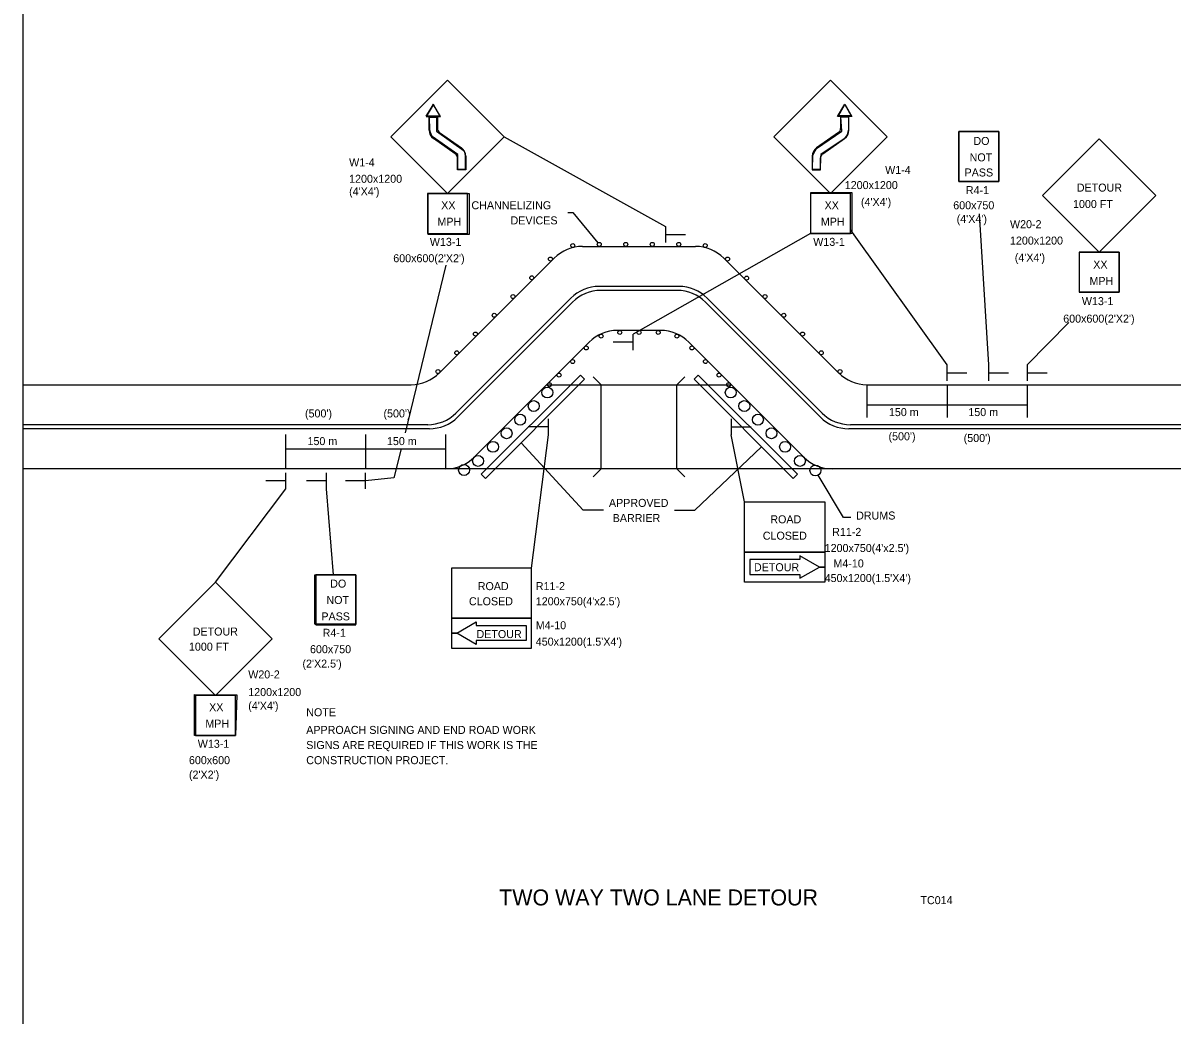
# Model space of a CAD drawing. Extents: x 1100953.92 to 1100956.78, y 416755.57 to 416757.4.
# Drawn here: x 1100955.836 to 1100956.434, y 416756.372 to 416756.888 of the extents above; entities that cross this region are included whole.
import ezdxf

# ---------------------------------------------------------------- set-up
doc = ezdxf.new("R2010")
doc.units = 0
for name, color, linetype in [('GROUND TEXT', 7, 'Continuous'), ('H_V CNTRL TEXT', 7, 'Continuous'), ('H_V CONTROLS', 7, 'Continuous'), ('Level 11', 7, 'Continuous'), ('Level 33', 7, 'Continuous'), ('Level 5', 7, 'Continuous'), ('ORIG TOPO TEXT', 7, 'Continuous')]:
    doc.layers.add(name, color=color, linetype=linetype)

msp = doc.modelspace()

# ---------------------------------------------------------------- linework, layer by layer
at = {"layer": 'GROUND TEXT'}
for centre in [(1100956.10844, 416756.69561), (1100956.20386, 416756.69561), (1100956.10137, 416756.68855), (1100956.21093, 416756.68855), (1100956.09431, 416756.68148), (1100956.21799, 416756.68148), (1100956.08724, 416756.67442), (1100956.22506, 416756.67442), (1100956.08018, 416756.66735), (1100956.23212, 416756.66735), (1100956.07243, 416756.66003), (1100956.23987, 416756.66003), (1100956.06513, 416756.6553), (1100956.2479, 416756.65504)]:
    msp.add_circle(centre, 0.00284, dxfattribs=at)
at = {"layer": 'H_V CNTRL TEXT'}
for p, q in [((1100956.1268, 416756.77166), (1100956.1855, 416756.77166)), ((1100956.0523, 416756.70579), (1100956.11207, 416756.76556)), ((1100956.20023, 416756.76556), (1100956.26, 416756.70579)), ((1100956.17687, 416756.75083), (1100956.13543, 416756.75083)), ((1100956.17601, 416756.74875), (1100956.13629, 416756.74875)), ((1100956.1207, 416756.74473), (1100956.06093, 416756.68496)), ((1100956.12156, 416756.74264), (1100956.06179, 416756.68287)), ((1100956.25051, 416756.68287), (1100956.19074, 416756.74264)), ((1100956.25137, 416756.68496), (1100956.1916, 416756.74473)), ((1100956.16738, 416756.72791), (1100956.14492, 416756.72791)), ((1100956.13019, 416756.72181), (1100956.07042, 416756.66204)), ((1100956.24188, 416756.66204), (1100956.18211, 416756.72181)), ((1100955.83571, 416756.69969), (1100956.03757, 416756.69969)), ((1100956.10807, 416756.69969), (1100956.20423, 416756.69969)), ((1100956.27473, 416756.69969), (1100956.45743, 416756.69969)), ((1100956.27473, 416756.69969), (1100956.27473, 416756.68266)), ((1100956.3164, 416756.69969), (1100956.3164, 416756.68266)), ((1100956.35807, 416756.69969), (1100956.35807, 416756.68266)), ((1100956.04619, 416756.67885), (1100955.83571, 416756.67885)), ((1100956.04706, 416756.67677), (1100955.83571, 416756.67677)), ((1100956.45743, 416756.67677), (1100956.26524, 416756.67677)), ((1100956.45743, 416756.67885), (1100956.2661, 416756.67885)), ((1100955.97235, 416756.65594), (1100955.97235, 416756.67383)), ((1100956.01402, 416756.65594), (1100956.01402, 416756.67383)), ((1100956.05569, 416756.65594), (1100956.05569, 416756.67383)), ((1100956.05569, 416756.65594), (1100955.83571, 416756.65594)), ((1100956.25661, 416756.65594), (1100956.05569, 416756.65594)), ((1100956.45743, 416756.65594), (1100956.25661, 416756.65594))]:
    msp.add_line(p, q, dxfattribs=at)
for points in [[(1100956.11908, 416756.78927), (1100956.12174, 416756.78927), (1100956.13479, 416756.77351)], [(1100956.12783, 416756.70249), (1100956.12562, 416756.7047), (1100956.07406, 416756.65314), (1100956.07627, 416756.65093), (1100956.12783, 416756.70249)], [(1100956.18697, 416756.7047), (1100956.18476, 416756.70249), (1100956.23632, 416756.65093), (1100956.23853, 416756.65314), (1100956.18697, 416756.7047)], [(1100956.13232, 416756.65177), (1100956.13648, 416756.65594), (1100956.13648, 416756.69969), (1100956.13232, 416756.70385)], [(1100956.17998, 416756.65177), (1100956.17582, 416756.65594), (1100956.17582, 416756.69969), (1100956.17998, 416756.70385)], [(1100956.13775, 416756.63434), (1100956.12705, 416756.63434), (1100956.09477, 416756.66943)], [(1100956.17455, 416756.63434), (1100956.18525, 416756.63434), (1100956.21987, 416756.66738)], [(1100956.26637, 416756.6306), (1100956.26257, 416756.6306), (1100956.24936, 416756.6526)]]:
    msp.add_lwpolyline(points, dxfattribs=at)
for centre, start, end in [((1100956.1268, 416756.75083), 90, 135), ((1100956.1855, 416756.75083), 45, 90), ((1100956.13543, 416756.73), 90, 135), ((1100956.13629, 416756.72791), 90, 135), ((1100956.17601, 416756.72791), 45, 90), ((1100956.17687, 416756.73), 45, 90), ((1100956.14492, 416756.70708), 90, 135), ((1100956.16738, 416756.70708), 45, 90), ((1100956.03757, 416756.72052), 270, 315), ((1100956.27473, 416756.72052), 225, 270), ((1100956.04619, 416756.69969), 270, 315), ((1100956.04706, 416756.6976), 270, 315), ((1100956.26524, 416756.6976), 225, 270), ((1100956.2661, 416756.69969), 225, 270), ((1100956.05569, 416756.67677), 270, 315), ((1100956.25661, 416756.67677), 225, 270)]:
    msp.add_arc(centre, 0.02083, start, end, dxfattribs=at)
at = {"layer": 'Level 11'}
for p, q in [((1100956.26101, 416756.83923), (1100956.26101, 416756.83304)), ((1100956.05239, 416756.8309), (1100956.0638, 416756.8229)), ((1100956.25991, 416756.8309), (1100956.2485, 416756.8229)), ((1100956.06057, 416756.81987), (1100956.04916, 416756.82787)), ((1100956.08594, 416756.82863), (1100956.16985, 416756.78198)), ((1100956.25173, 416756.81987), (1100956.26314, 416756.82787)), ((1100956.34325, 416756.80533), (1100956.34337, 416756.80544)), ((1100956.33316, 416756.78867), (1100956.33791, 416756.71004)), ((1100956.2454, 416756.77834), (1100956.15316, 416756.72605)), ((1100956.16985, 416756.78198), (1100956.16985, 416756.77365)), ((1100956.16985, 416756.77781), (1100956.18027, 416756.77781)), ((1100956.26623, 416756.78012), (1100956.31629, 416756.71004)), ((1100956.38507, 416756.76865), (1100956.38507, 416756.74781)), ((1100956.05571, 416756.76186), (1100956.0344, 416756.67469)), ((1100956.3797, 416756.73198), (1100956.35806, 416756.71004)), ((1100956.15316, 416756.71772), (1100956.15316, 416756.72605)), ((1100956.15316, 416756.72189), (1100956.14274, 416756.72189)), ((1100956.31629, 416756.71004), (1100956.31629, 416756.7017)), ((1100956.31629, 416756.70587), (1100956.3267, 416756.70587)), ((1100956.33791, 416756.71004), (1100956.33791, 416756.7017)), ((1100956.33791, 416756.70587), (1100956.34833, 416756.70587)), ((1100956.35806, 416756.71004), (1100956.35806, 416756.7017)), ((1100956.35806, 416756.70587), (1100956.36848, 416756.70587)), ((1100956.27473, 416756.68927), (1100956.3164, 416756.68927)), ((1100956.3164, 416756.68927), (1100956.35807, 416756.68927)), ((1100956.10898, 416756.67365), (1100956.10898, 416756.68198)), ((1100956.20416, 416756.68198), (1100956.20416, 416756.67365)), ((1100956.10898, 416756.67781), (1100956.09856, 416756.67781)), ((1100956.20416, 416756.67781), (1100956.21457, 416756.67781)), ((1100956.10022, 416756.60429), (1100956.10898, 416756.67365)), ((1100956.21109, 416756.63868), (1100956.20416, 416756.67365)), ((1100955.97235, 416756.66635), (1100956.01402, 416756.66635)), ((1100956.01402, 416756.66635), (1100956.05569, 416756.66635)), ((1100955.97242, 416756.64548), (1100955.97242, 416756.65381)), ((1100955.99359, 416756.64548), (1100955.99359, 416756.65381)), ((1100956.01392, 416756.64548), (1100956.01392, 416756.65381)), ((1100955.93581, 416756.59698), (1100955.97242, 416756.64548)), ((1100955.97242, 416756.64964), (1100955.962, 416756.64964)), ((1100955.99359, 416756.64964), (1100955.98317, 416756.64964)), ((1100955.99728, 416756.60077), (1100955.99359, 416756.64548)), ((1100956.01392, 416756.64964), (1100956.0035, 416756.64964)), ((1100955.98805, 416756.57473), (1100955.98793, 416756.57485))]:
    msp.add_line(p, q, dxfattribs=at)
for points in [[(1100956.02702, 416756.82863), (1100956.05648, 416756.79917), (1100956.08594, 416756.82863), (1100956.05648, 416756.8581), (1100956.02702, 416756.82863)], [(1100956.28528, 416756.82863), (1100956.25582, 416756.79917), (1100956.22636, 416756.82863), (1100956.25582, 416756.8581), (1100956.28528, 416756.82863)], [(1100956.04536, 416756.83923), (1100956.05286, 416756.83923), (1100956.04911, 416756.84573), (1100956.04536, 416756.83923)], [(1100956.26693, 416756.83923), (1100956.25943, 416756.83923), (1100956.26318, 416756.84573), (1100956.26693, 416756.83923)], [(1100956.04694, 416756.83213), (1100956.04694, 416756.83923), (1100956.05129, 416756.83923), (1100956.05129, 416756.83304)], [(1100956.26535, 416756.83213), (1100956.26535, 416756.83923), (1100956.26101, 416756.83923)], [(1100956.34337, 416756.83137), (1100956.34337, 416756.80533), (1100956.32254, 416756.80533), (1100956.32254, 416756.83137), (1100956.34337, 416756.83137)], [(1100956.32254, 416756.83137), (1100956.32254, 416756.80533), (1100956.34337, 416756.80533), (1100956.34337, 416756.83137), (1100956.32254, 416756.83137)], [(1100956.42495, 416756.79811), (1100956.39549, 416756.76865), (1100956.36603, 416756.79811), (1100956.39549, 416756.82757), (1100956.42495, 416756.79811)], [(1100956.06602, 416756.81864), (1100956.06602, 416756.81154), (1100956.06168, 416756.81154), (1100956.06168, 416756.81773)], [(1100956.24628, 416756.81864), (1100956.24628, 416756.81154), (1100956.25062, 416756.81154), (1100956.25062, 416756.81773)], [(1100956.0669, 416756.79917), (1100956.04606, 416756.79917), (1100956.04606, 416756.77834), (1100956.0669, 416756.77834), (1100956.0669, 416756.79917)], [(1100956.04606, 416756.79917), (1100956.04606, 416756.77834), (1100956.0669, 416756.77834), (1100956.0669, 416756.79917), (1100956.04606, 416756.79917)], [(1100956.2454, 416756.79917), (1100956.2454, 416756.77834), (1100956.26623, 416756.77834), (1100956.26623, 416756.79917), (1100956.2454, 416756.79917)], [(1100956.2454, 416756.77834), (1100956.26623, 416756.77834), (1100956.26623, 416756.79917), (1100956.2454, 416756.79917), (1100956.2454, 416756.77834)], [(1100956.38507, 416756.76865), (1100956.40591, 416756.76865), (1100956.40591, 416756.74781), (1100956.38507, 416756.74781)], [(1100956.38507, 416756.76865), (1100956.38507, 416756.74781), (1100956.40591, 416756.74781), (1100956.40591, 416756.76865), (1100956.38507, 416756.76865)], [(1100956.03236, 416756.66635), (1100956.02866, 416756.65121), (1100956.01392, 416756.64964)], [(1100956.25275, 416756.63868), (1100956.25275, 416756.61264), (1100956.21109, 416756.61264), (1100956.21109, 416756.63868), (1100956.25275, 416756.63868)], [(1100956.25275, 416756.61264), (1100956.25275, 416756.60483), (1100956.24998, 416756.60483), (1100956.23983, 416756.61069), (1100956.23983, 416756.60873), (1100956.21386, 416756.60873), (1100956.21386, 416756.60092), (1100956.23983, 416756.60092), (1100956.23983, 416756.59897), (1100956.24998, 416756.60483), (1100956.25275, 416756.60483), (1100956.25275, 416756.59701), (1100956.21109, 416756.59701), (1100956.21109, 416756.61264), (1100956.25275, 416756.61264)], [(1100956.24998, 416756.60483), (1100956.23983, 416756.61069), (1100956.23983, 416756.60873), (1100956.21386, 416756.60873), (1100956.21386, 416756.60092), (1100956.23983, 416756.60092), (1100956.23983, 416756.59897), (1100956.24998, 416756.60483)], [(1100956.05856, 416756.60429), (1100956.05856, 416756.57825), (1100956.10022, 416756.57825), (1100956.10022, 416756.60429), (1100956.05856, 416756.60429)], [(1100955.90635, 416756.56751), (1100955.93581, 416756.53805), (1100955.96528, 416756.56751), (1100955.93581, 416756.59698), (1100955.90635, 416756.56751)], [(1100955.98793, 416756.60077), (1100955.98793, 416756.57473), (1100956.00877, 416756.57473), (1100956.00877, 416756.60077), (1100955.98793, 416756.60077)], [(1100956.05856, 416756.57825), (1100956.05856, 416756.57044), (1100956.06133, 416756.57044), (1100956.07148, 416756.5763), (1100956.07148, 416756.57434), (1100956.09745, 416756.57434), (1100956.09745, 416756.56653), (1100956.07148, 416756.56653), (1100956.07148, 416756.56458), (1100956.06133, 416756.57044), (1100956.05856, 416756.57044), (1100956.05856, 416756.56262), (1100956.10022, 416756.56262), (1100956.10022, 416756.57825), (1100956.05856, 416756.57825)], [(1100956.06133, 416756.57044), (1100956.07148, 416756.5763), (1100956.07148, 416756.57434), (1100956.09745, 416756.57434), (1100956.09745, 416756.56653), (1100956.07148, 416756.56653), (1100956.07148, 416756.56458), (1100956.06133, 416756.57044)], [(1100955.9254, 416756.53805), (1100955.9254, 416756.51722), (1100955.94623, 416756.51722), (1100955.94623, 416756.53805), (1100955.9254, 416756.53805)], [(1100955.94623, 416756.51722), (1100955.94623, 416756.53805), (1100955.9254, 416756.53805), (1100955.9254, 416756.51722), (1100955.94623, 416756.51722)]]:
    msp.add_lwpolyline(points, dxfattribs=at)
for centre, radius, start, end in [((1100956.05215, 416756.83213), 0.00521, 180, 234.94043), ((1100956.05389, 416756.83304), 0.0026, 180, 234.94044), ((1100956.25841, 416756.83304), 0.0026, 305.05957, 0), ((1100956.26015, 416756.83213), 0.00521, 305.05957, 360), ((1100956.05907, 416756.81773), 0.0026, 360, 54.94043), ((1100956.06081, 416756.81864), 0.00521, 360, 54.94043), ((1100956.25149, 416756.81864), 0.00521, 125.05957, 180), ((1100956.25323, 416756.81773), 0.0026, 125.05956, 180)]:
    msp.add_arc(centre, radius, start, end, dxfattribs=at)
at = {"layer": 'Level 33'}
for points in [[(1100956.04651, 416756.7992), (1100956.06784, 416756.7992), (1100956.06784, 416756.77787), (1100956.04651, 416756.77787), (1100956.04651, 416756.7992)], [(1100956.24555, 416756.79962), (1100956.26688, 416756.79962), (1100956.26688, 416756.77829), (1100956.24555, 416756.77829), (1100956.24555, 416756.79962)], [(1100955.98743, 416756.60074), (1100955.98743, 416756.60074), (1100956.00877, 416756.60074), (1100956.00877, 416756.57504), (1100955.98743, 416756.57504), (1100955.98743, 416756.59638)], [(1100955.92555, 416756.53825), (1100955.94688, 416756.53825), (1100955.94623, 416756.51722), (1100955.9249, 416756.51722), (1100955.9249, 416756.53855)]]:
    msp.add_lwpolyline(points, close=True, dxfattribs=at)
at = {"layer": 'Level 5'}
for centre in [(1100956.12171, 416756.7721), (1100956.13546, 416756.7727), (1100956.14925, 416756.7727), (1100956.16305, 416756.7727), (1100956.17684, 416756.7727), (1100956.19059, 416756.7721), (1100956.11009, 416756.76506), (1100956.20221, 416756.76506), (1100956.10034, 416756.7553), (1100956.21214, 416756.75512), (1100956.09058, 416756.74555), (1100956.22172, 416756.74555), (1100956.08083, 416756.73579), (1100956.23147, 416756.73579), (1100956.07107, 416756.72604), (1100956.13645, 416756.72497), (1100956.14616, 416756.72687), (1100956.15615, 416756.72687), (1100956.16614, 416756.72687), (1100956.17585, 416756.72497), (1100956.24123, 416756.72604), (1100956.06132, 416756.71628), (1100956.12866, 416756.71881), (1100956.18364, 416756.71881), (1100956.25098, 416756.71628), (1100956.1216, 416756.71175), (1100956.1907, 416756.71175), (1100956.05156, 416756.70653), (1100956.11453, 416756.70468), (1100956.19777, 416756.70468), (1100956.26074, 416756.70653), (1100956.10954, 416756.69969), (1100956.20276, 416756.69969)]:
    msp.add_circle(centre, 0.00104, dxfattribs=at)
at = {"layer": 'ORIG TOPO TEXT'}
for points in [[(1100955.83565, 416756.95507), (1100955.83565, 416756.3569), (1100956.46304, 416756.3569), (1100956.46304, 416756.95507), (1100955.83565, 416756.95507)], [(1100956.04911, 416756.84573), (1100956.0525, 416756.83947), (1100956.04539, 416756.83939), (1100956.04921, 416756.84539)]]:
    msp.add_lwpolyline(points, dxfattribs=at)
for points in [[(1100956.04917, 416756.84535), (1100956.05251, 416756.83936), (1100956.04566, 416756.8393)], [(1100956.2632, 416756.84542), (1100956.26648, 416756.83952), (1100956.25992, 416756.83952)], [(1100956.04721, 416756.83896), (1100956.05085, 416756.83896), (1100956.05085, 416756.83154), (1100956.06515, 416756.82136), (1100956.06576, 416756.81895), (1100956.06576, 416756.8117), (1100956.06186, 416756.8117), (1100956.06186, 416756.81938), (1100956.04851, 416756.82887), (1100956.04773, 416756.83094), (1100956.04728, 416756.83214)], [(1100956.2611, 416756.83908), (1100956.26521, 416756.83908), (1100956.26521, 416756.83226), (1100956.26445, 416756.82976), (1100956.26288, 416756.82767), (1100956.25082, 416756.81938), (1100956.25059, 416756.81802), (1100956.25044, 416756.81158), (1100956.24648, 416756.81167), (1100956.24665, 416756.81893), (1100956.24785, 416756.82135), (1100956.24848, 416756.82263), (1100956.26163, 416756.83166)]]:
    msp.add_lwpolyline(points, close=True, dxfattribs=at)

# ---------------------------------------------------------------- texts
at = {"layer": 'H_V CNTRL TEXT'}
for s, height, p in [('CHANNELIZING', 0.0041654, (1100956.06897, 416756.79096)), ('DEVICES', 0.004165, (1100956.08931, 416756.78309)), ('APPROVED', 0.004165, (1100956.1405, 416756.6361)), ('DRUMS', 0.004165, (1100956.2691, 416756.62954)), ('BARRIER', 0.004165, (1100956.14246, 416756.62823)), ('NOTE', 0.004165, (1100955.98301, 416756.52718)), ('APPROACH SIGNING AND END ROAD WORK', 0.0041654, (1100955.98301, 416756.51799)), ('SIGNS ARE REQUIRED IF THIS WORK IS THE', 0.0041654, (1100955.98301, 416756.51012)), ('CONSTRUCTION PROJECT.', 0.0041654, (1100955.98301, 416756.50225))]:
    msp.add_text(s, height=height, dxfattribs=at).set_placement(p)
at = {"layer": 'H_V CONTROLS'}
for s, height, p in [('TWO WAY TWO LANE DETOUR', 0.0083307, (1100956.08341, 416756.42875)), ('TC014', 0.004165, (1100956.30257, 416756.42941))]:
    msp.add_text(s, height=height, dxfattribs=at).set_placement(p)
at = {"layer": 'Level 11'}
for s, height, p in [('DO', 0.004165, (1100956.33013, 416756.82442)), ('NOT', 0.004165, (1100956.32816, 416756.81589)), ('W1-4', 0.004165, (1100956.00532, 416756.81327)), ('W1-4', 0.004165, (1100956.2842, 416756.80933)), ('PASS', 0.004165, (1100956.32553, 416756.80802)), ('1200x1200', 0.004165, (1100956.00532, 416756.80474)), ("(4'X4')", 0.004165, (1100956.00532, 416756.79817)), ('1200x1200', 0.004165, (1100956.2632, 416756.80146)), ('R4-1', 0.004165, (1100956.32619, 416756.79883)), ('DETOUR', 0.004165, (1100956.38393, 416756.80015)), ('XX', 0.004165, (1100956.05322, 416756.79096)), ('XX', 0.004165, (1100956.2527, 416756.79096)), ("(4'X4')", 0.004165, (1100956.27161, 416756.79268)), ('600x750', 0.004165, (1100956.31963, 416756.79096)), ('1000 FT', 0.004165, (1100956.38196, 416756.79162)), ("(4'X4')", 0.004165, (1100956.32142, 416756.78386)), ('MPH', 0.004165, (1100956.05126, 416756.78243)), ('MPH', 0.004165, (1100956.25073, 416756.78243)), ('W20-2', 0.004165, (1100956.34916, 416756.78112)), ('1200x1200', 0.004165, (1100956.34916, 416756.77259)), ('W13-1', 0.004165, (1100956.04732, 416756.77193)), ('W13-1', 0.004165, (1100956.24679, 416756.77193)), ("600x600(2'X2')", 0.0041654, (1100956.02829, 416756.7634)), ("(4'X4')", 0.004165, (1100956.35165, 416756.76378)), ('XX', 0.004165, (1100956.39246, 416756.76012)), ('MPH', 0.004165, (1100956.3905, 416756.75159)), ('W13-1', 0.004165, (1100956.38656, 416756.74109)), ("600x600(2'X2')", 0.0041654, (1100956.37685, 416756.73198)), ("(500')", 0.004165, (1100955.98236, 416756.68266)), ("(500')", 0.004165, (1100956.02321, 416756.68266)), ('150 m', 0.004165, (1100956.28616, 416756.68335)), ('150 m', 0.004165, (1100956.3275, 416756.68335)), ("(500')", 0.004165, (1100956.28596, 416756.67076)), ('150 m', 0.004165, (1100955.98367, 416756.66826)), ('150 m', 0.004165, (1100956.02501, 416756.66826)), ("(500')", 0.004165, (1100956.32506, 416756.66988)), ('ROAD', 0.004165, (1100956.22448, 416756.62757)), ('CLOSED', 0.004165, (1100956.22055, 416756.61904)), ('R11-2', 0.004165, (1100956.25664, 416756.62101)), ("1200x750(4'x2.5')", 0.0041654, (1100956.25275, 416756.61264)), ('M4-10', 0.004165, (1100956.25729, 416756.60461)), ('DETOUR', 0.004165, (1100956.21595, 416756.60264)), ('DO', 0.004165, (1100955.99548, 416756.59411)), ('ROAD', 0.004165, (1100956.07225, 416756.5928)), ('R11-2', 0.004165, (1100956.10244, 416756.5928)), ("450x1200(1.5'X4')", 0.0041654, (1100956.25275, 416756.59701)), ('NOT', 0.004165, (1100955.99351, 416756.58558)), ('CLOSED', 0.004165, (1100956.06766, 416756.58492)), ("1200x750(4'x2.5')", 0.0041654, (1100956.10244, 416756.58492)), ('PASS', 0.004165, (1100955.99089, 416756.57705)), ('DETOUR', 0.004165, (1100955.92396, 416756.56917)), ('M4-10', 0.004165, (1100956.10244, 416756.57246)), ('R4-1', 0.004165, (1100955.99155, 416756.56852)), ('DETOUR', 0.004165, (1100956.0716, 416756.56786)), ("450x1200(1.5'X4')", 0.0041654, (1100956.10244, 416756.56392)), ('1000 FT', 0.004165, (1100955.92199, 416756.5613)), ('600x750', 0.004165, (1100955.98498, 416756.55999)), ("(2'X2.5')", 0.004165, (1100955.98105, 416756.55249)), ('W20-2', 0.004165, (1100955.95283, 416756.54686)), ('1200x1200', 0.004165, (1100955.95283, 416756.53768)), ('XX', 0.004165, (1100955.93249, 416756.5298)), ("(4'X4')", 0.004165, (1100955.95283, 416756.53056)), ('MPH', 0.004165, (1100955.93052, 416756.52127)), ('W13-1', 0.004165, (1100955.92658, 416756.51078)), ('600x600', 0.004165, (1100955.92199, 416756.50225)), ("(2'X2')", 0.004165, (1100955.92199, 416756.49475))]:
    msp.add_text(s, height=height, dxfattribs=at).set_placement(p)

doc.saveas('drawing.dxf')
